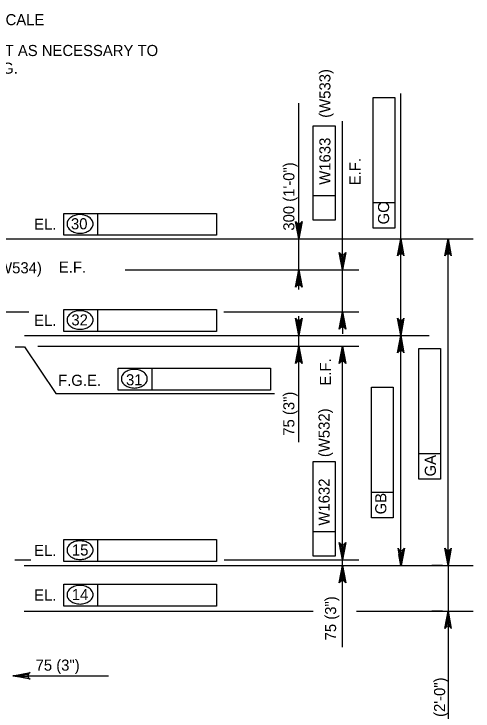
# Model space of a CAD drawing. Extents: x 634540 to 640306, y 296059 to 300275.
# Drawn here: x 638903.8 to 639027.8, y 296158.8 to 296347 of the extents above; entities that cross this region are included whole.
import ezdxf

# ---------------------------------------------------------------- set-up
doc = ezdxf.new("R2010")
doc.units = 0
doc.layers.add('3', color=7, linetype='Continuous')
doc.layers.add('4', color=7, linetype='Continuous')

msp = doc.modelspace()

# ---------------------------------------------------------------- linework, layer by layer
at = {"layer": '3'}
msp.add_line((638904.09, 296257.12), (638906.63, 296257.12), dxfattribs=at)
at = {"layer": '4'}
for p, q in [((639008.26, 296263.15), (639008.26, 296325.58)), ((639000.79, 296289.14), (639000.79, 296324.44)), ((639000.79, 296324.44), (639006.7, 296324.44)), ((639006.7, 296324.44), (639006.7, 296289.14)), ((638980.71, 296272.65), (638980.71, 296322.97)), ((638992.52, 296288.56), (638992.52, 296318.07)), ((638984.63, 296291.3), (638984.63, 296316.84)), ((638984.63, 296316.84), (638990.54, 296316.84)), ((638990.54, 296316.84), (638990.54, 296291.3)), ((638990.54, 296297.89), (638984.63, 296297.89)), ((639006.7, 296295.98), (639000.79, 296295.98)), ((638917.24, 296293.18), (638958.46, 296293.18)), ((638917.24, 296287.27), (638917.24, 296293.18)), ((638926.41, 296287.27), (638926.41, 296293.18)), ((638958.46, 296293.18), (638958.46, 296287.27)), ((638990.54, 296291.3), (638984.63, 296291.3)), ((638992.52, 296280.88), (638992.52, 296288.56)), ((639006.7, 296289.14), (639000.79, 296289.14)), ((638834.74, 296286.34), (639027.79, 296286.34)), ((638958.46, 296287.27), (638917.24, 296287.27)), ((639005.79, 296286.34), (639012.68, 296286.34)), ((639014.71, 296286.34), (639025.47, 296286.34)), ((639021.04, 296198.06), (639021.04, 296286.34)), ((638933.76, 296277.93), (638996.95, 296277.93)), ((638992.52, 296266.56), (638992.52, 296277.93)), ((638917.24, 296267.21), (638958.46, 296267.21)), ((638917.24, 296261.31), (638917.24, 296267.21)), ((638926.41, 296261.31), (638926.41, 296267.21)), ((638958.46, 296267.21), (638958.46, 296261.31)), ((638893.78, 296266.56), (638907.75, 296266.56)), ((638960.47, 296266.56), (638996.95, 296266.56)), ((638980.71, 296231.4), (638980.71, 296265.39)), ((638992.52, 296263.6), (638992.52, 296260.65)), ((638958.46, 296261.31), (638917.24, 296261.31)), ((638906.65, 296260.2), (639015.91, 296260.2)), ((639002.91, 296260.2), (639012.68, 296260.2)), ((638910.23, 296257.33), (638996.95, 296257.33)), ((638906.63, 296257.12), (638915.1, 296244.52)), ((639008.26, 296201.02), (639008.26, 296257.25)), ((639013.13, 296221.4), (639013.13, 296256.7)), ((639013.13, 296256.7), (639019.03, 296256.7)), ((639019.03, 296256.7), (639019.03, 296221.4)), ((638992.52, 296175.97), (638992.52, 296254.38)), ((638931.9, 296245.45), (638931.9, 296251.36)), ((638931.9, 296251.36), (638973.11, 296251.36)), ((638941.07, 296245.45), (638941.07, 296251.36)), ((638973.11, 296251.36), (638973.11, 296245.45)), ((639000.34, 296210.91), (639000.34, 296246.21)), ((639000.34, 296246.21), (639006.24, 296246.21)), ((639006.24, 296246.21), (639006.24, 296210.91)), ((638915.1, 296244.52), (638974.12, 296244.52)), ((638973.11, 296245.45), (638931.9, 296245.45)), ((639019.03, 296228.24), (639013.13, 296228.24)), ((638984.63, 296200.59), (638984.63, 296226.13)), ((638984.63, 296226.13), (638990.54, 296226.13)), ((638990.54, 296226.13), (638990.54, 296200.59)), ((639019.03, 296221.4), (639013.13, 296221.4)), ((639006.24, 296217.75), (639000.34, 296217.75)), ((639006.24, 296210.91), (639000.34, 296210.91)), ((638990.54, 296207.19), (638984.63, 296207.19)), ((638917.24, 296205.07), (638958.46, 296205.07)), ((638917.24, 296199.16), (638917.24, 296205.07)), ((638926.41, 296199.16), (638926.41, 296205.07)), ((638958.46, 296205.07), (638958.46, 296199.16)), ((638904.01, 296199.6), (638908.28, 296199.6)), ((638958.46, 296199.16), (638917.24, 296199.16)), ((638960.53, 296199.6), (638996.95, 296199.6)), ((638990.54, 296200.59), (638984.63, 296200.59)), ((638906.49, 296198.06), (639027.79, 296198.06)), ((639002.91, 296198.06), (639012.68, 296198.06)), ((639014.71, 296198.06), (639025.47, 296198.06)), ((639019.57, 296198.06), (639016.61, 296198.06)), ((639021.04, 296198.06), (639021.04, 296185.76)), ((638917.24, 296193.02), (638958.46, 296193.02)), ((638917.24, 296187.11), (638917.24, 296193.02)), ((638926.41, 296187.11), (638926.41, 296193.02)), ((638958.46, 296193.02), (638958.46, 296187.11)), ((638906.49, 296185.76), (638984.56, 296185.76)), ((638958.46, 296187.11), (638917.24, 296187.11)), ((638996.29, 296185.76), (639027.79, 296185.76)), ((639019.57, 296185.76), (639016.61, 296185.76)), ((639021.04, 296182.81), (639021.04, 296149.36)), ((638906.45, 296168.29), (638909.41, 296168.29)), ((638909.41, 296168.29), (638929.26, 296168.29))]:
    msp.add_line(p, q, dxfattribs=at)
for points in [[(638980.71, 296286.34), (638979.84, 296291), (638980.09, 296290.65), (638980.4, 296290.46), (638980.71, 296290.41), (638981.02, 296290.46), (638981.34, 296290.65), (638981.59, 296291), (638980.71, 296286.34), (638981.34, 296290.65), (638981.02, 296290.46), (638980.71, 296286.34), (638980.71, 296290.41), (638980.4, 296290.46), (638980.71, 296286.34), (638980.09, 296290.65)], [(639008.26, 296286.34), (639009.13, 296281.68), (639008.88, 296282.04), (639008.57, 296282.23), (639008.26, 296282.28), (639007.94, 296282.23), (639007.63, 296282.04), (639007.38, 296281.68), (639008.26, 296286.34), (639007.63, 296282.04), (639007.94, 296282.23), (639008.26, 296286.34), (639008.26, 296282.28), (639008.57, 296282.23), (639008.26, 296286.34), (639008.88, 296282.04)], [(639021.04, 296286.34), (639021.91, 296281.68), (639021.67, 296282.04), (639021.35, 296282.23), (639021.04, 296282.28), (639020.73, 296282.23), (639020.42, 296282.04), (639020.17, 296281.68), (639021.04, 296286.34), (639020.42, 296282.04), (639020.73, 296282.23), (639021.04, 296286.34), (639021.04, 296282.28), (639021.35, 296282.23), (639021.04, 296286.34), (639021.67, 296282.04)], [(638992.52, 296277.93), (638991.65, 296282.59), (638991.9, 296282.23), (638992.21, 296282.05), (638992.52, 296281.99), (638992.84, 296282.05), (638993.15, 296282.23), (638993.4, 296282.59), (638992.52, 296277.93), (638993.15, 296282.23), (638992.84, 296282.05), (638992.52, 296277.93), (638992.52, 296281.99), (638992.21, 296282.05), (638992.52, 296277.93), (638991.9, 296282.23)], [(638980.71, 296277.93), (638981.59, 296273.27), (638981.34, 296273.63), (638981.02, 296273.81), (638980.71, 296273.87), (638980.4, 296273.81), (638980.09, 296273.63), (638979.84, 296273.27), (638980.71, 296277.93), (638980.09, 296273.63), (638980.4, 296273.81), (638980.71, 296277.93), (638980.71, 296273.87), (638981.02, 296273.81), (638980.71, 296277.93), (638981.34, 296273.63)], [(638980.71, 296260.2), (638979.84, 296264.86), (638980.09, 296264.5), (638980.4, 296264.31), (638980.71, 296264.26), (638981.02, 296264.31), (638981.34, 296264.5), (638981.59, 296264.86), (638980.71, 296260.2), (638981.34, 296264.5), (638981.02, 296264.31), (638980.71, 296260.2), (638980.71, 296264.26), (638980.4, 296264.31), (638980.71, 296260.2), (638980.09, 296264.5)], [(638992.52, 296266.56), (638993.4, 296261.9), (638993.15, 296262.26), (638992.84, 296262.44), (638992.52, 296262.5), (638992.21, 296262.44), (638991.9, 296262.26), (638991.65, 296261.9), (638992.52, 296266.56), (638991.9, 296262.26), (638992.21, 296262.44), (638992.52, 296266.56), (638992.52, 296262.5), (638992.84, 296262.44), (638992.52, 296266.56), (638993.15, 296262.26)], [(639008.26, 296260.2), (639007.38, 296264.86), (639007.63, 296264.5), (639007.94, 296264.31), (639008.26, 296264.26), (639008.57, 296264.31), (639008.88, 296264.5), (639009.13, 296264.86), (639008.26, 296260.2), (639008.88, 296264.5), (639008.57, 296264.31), (639008.26, 296260.2), (639008.26, 296264.26), (639007.94, 296264.31), (639008.26, 296260.2), (639007.63, 296264.5)], [(639008.26, 296260.2), (639009.13, 296255.54), (639008.88, 296255.9), (639008.57, 296256.08), (639008.26, 296256.14), (639007.94, 296256.08), (639007.63, 296255.9), (639007.38, 296255.54), (639008.26, 296260.2), (639007.63, 296255.9), (639007.94, 296256.08), (639008.26, 296260.2), (639008.26, 296256.14), (639008.57, 296256.08), (639008.26, 296260.2), (639008.88, 296255.9)], [(638980.71, 296257.33), (638981.59, 296252.67), (638981.34, 296253.03), (638981.02, 296253.21), (638980.71, 296253.27), (638980.4, 296253.21), (638980.09, 296253.03), (638979.84, 296252.67), (638980.71, 296257.33), (638980.09, 296253.03), (638980.4, 296253.21), (638980.71, 296257.33), (638980.71, 296253.27), (638981.02, 296253.21), (638980.71, 296257.33), (638981.34, 296253.03)], [(638992.52, 296257.33), (638993.4, 296252.67), (638993.15, 296253.03), (638992.84, 296253.21), (638992.52, 296253.27), (638992.21, 296253.21), (638991.9, 296253.03), (638991.65, 296252.67), (638992.52, 296257.33), (638991.9, 296253.03), (638992.21, 296253.21), (638992.52, 296257.33), (638992.52, 296253.27), (638992.84, 296253.21), (638992.52, 296257.33), (638993.15, 296253.03)], [(638992.52, 296199.6), (638991.65, 296204.26), (638991.9, 296203.91), (638992.21, 296203.72), (638992.52, 296203.67), (638992.84, 296203.72), (638993.15, 296203.91), (638993.4, 296204.26), (638992.52, 296199.6), (638993.15, 296203.91), (638992.84, 296203.72), (638992.52, 296199.6), (638992.52, 296203.67), (638992.21, 296203.72), (638992.52, 296199.6), (638991.9, 296203.91)], [(639008.4, 296198.06), (639007.53, 296202.72), (639007.78, 296202.37), (639008.09, 296202.18), (639008.4, 296202.13), (639008.72, 296202.18), (639009.03, 296202.37), (639009.28, 296202.72), (639008.4, 296198.06), (639009.03, 296202.37), (639008.72, 296202.18), (639008.4, 296198.06), (639008.4, 296202.13), (639008.09, 296202.18), (639008.4, 296198.06), (639007.78, 296202.37)], [(639021.04, 296198.06), (639020.17, 296202.72), (639020.42, 296202.37), (639020.73, 296202.18), (639021.04, 296202.13), (639021.35, 296202.18), (639021.67, 296202.37), (639021.91, 296202.72), (639021.04, 296198.06), (639021.67, 296202.37), (639021.35, 296202.18), (639021.04, 296198.06), (639021.04, 296202.13), (639020.73, 296202.18), (639021.04, 296198.06), (639020.42, 296202.37)], [(638992.52, 296198.06), (638993.4, 296193.4), (638993.15, 296193.76), (638992.84, 296193.95), (638992.52, 296194), (638992.21, 296193.95), (638991.9, 296193.76), (638991.65, 296193.4), (638992.52, 296198.06), (638991.9, 296193.76), (638992.21, 296193.95), (638992.52, 296198.06), (638992.52, 296194), (638992.84, 296193.95), (638992.52, 296198.06), (638993.15, 296193.76)], [(639021.04, 296185.76), (639021.91, 296181.1), (639021.67, 296181.46), (639021.35, 296181.64), (639021.04, 296181.7), (639020.73, 296181.64), (639020.42, 296181.46), (639020.17, 296181.1), (639021.04, 296185.76), (639020.42, 296181.46), (639020.73, 296181.64), (639021.04, 296185.76), (639021.04, 296181.7), (639021.35, 296181.64), (639021.04, 296185.76), (639021.67, 296181.46)], [(638903.5, 296168.29), (638908.16, 296169.16), (638907.8, 296168.91), (638907.62, 296168.6), (638907.56, 296168.29), (638907.62, 296167.97), (638907.8, 296167.66), (638908.16, 296167.41), (638903.5, 296168.29), (638907.8, 296167.66), (638907.62, 296167.97), (638903.5, 296168.29), (638907.56, 296168.29), (638907.62, 296168.6), (638903.5, 296168.29), (638907.8, 296168.91)]]:
    msp.add_lwpolyline(points, dxfattribs=at)
for points in [[(639007.76, 296283.39), (639008.75, 296283.39), (639008.26, 296286.34)], [(639020.55, 296283.39), (639021.53, 296283.39), (639021.04, 296286.34)], [(638992.03, 296280.88), (638993.02, 296280.88), (638992.52, 296277.93)], [(638980.22, 296274.98), (638981.21, 296274.98), (638980.71, 296277.93)], [(638992.03, 296263.6), (638993.02, 296263.6), (638992.52, 296266.56)], [(638980.22, 296263.15), (638981.21, 296263.15), (638980.71, 296260.2)], [(639007.76, 296263.15), (639008.75, 296263.15), (639008.26, 296260.2)], [(639007.76, 296257.25), (639008.75, 296257.25), (639008.26, 296260.2)], [(638980.22, 296254.38), (638981.21, 296254.38), (638980.71, 296257.33)], [(638992.03, 296254.38), (638993.02, 296254.38), (638992.52, 296257.33)], [(638992.03, 296202.56), (638993.02, 296202.56), (638992.52, 296199.6)], [(639007.76, 296201.02), (639008.75, 296201.02), (639008.26, 296198.06)], [(639020.55, 296201.02), (639021.53, 296201.02), (639021.04, 296198.06)], [(638992.03, 296195.11), (638993.02, 296195.11), (638992.52, 296198.06)], [(639020.55, 296182.81), (639021.53, 296182.81), (639021.04, 296185.76)], [(638906.45, 296168.78), (638906.45, 296167.79), (638903.5, 296168.29)]]:
    msp.add_lwpolyline(points, close=True, dxfattribs=at)
for centre, radius, start, end in [((638919.94, 296290.33), 1.83, 149.9767, 180), ((638920.75, 296289.87), 2.76, 125.6316, 149.9767), ((638921.28, 296289.13), 3.66, 106.5358, 125.6316), ((638921.62, 296287.97), 4.87, 90, 106.5358), ((638921.62, 296287.97), 4.87, 73.4642, 90), ((638921.97, 296289.13), 3.66, 54.3684, 73.4642), ((638922.49, 296289.87), 2.76, 30.0233, 54.3684), ((638923.3, 296290.33), 1.83, 0, 30.0233), ((638919.94, 296290.33), 1.83, 180, 210.0233), ((638920.75, 296290.8), 2.76, 210.0233, 234.3684), ((638922.49, 296290.8), 2.76, 305.6316, 329.9767), ((638923.3, 296290.33), 1.83, 329.9767, 0), ((638921.28, 296291.53), 3.66, 234.3684, 253.4642), ((638921.62, 296292.69), 4.87, 253.4642, 270), ((638921.62, 296292.69), 4.87, 270, 286.5358), ((638921.97, 296291.53), 3.66, 286.5358, 305.6316), ((638921.28, 296263.17), 3.66, 106.5358, 125.6316), ((638921.62, 296262.01), 4.87, 90, 106.5358), ((638921.62, 296262.01), 4.87, 73.4642, 90), ((638921.97, 296263.17), 3.66, 54.3684, 73.4642), ((638919.94, 296264.37), 1.83, 149.9767, 180), ((638920.75, 296263.9), 2.76, 125.6316, 149.9767), ((638922.49, 296263.9), 2.76, 30.0233, 54.3684), ((638923.3, 296264.37), 1.83, 0, 30.0233), ((638919.94, 296264.37), 1.83, 180, 210.0233), ((638920.75, 296264.83), 2.76, 210.0233, 234.3684), ((638922.49, 296264.83), 2.76, 305.6316, 329.9767), ((638923.3, 296264.37), 1.83, 329.9767, 0), ((638921.28, 296265.57), 3.66, 234.3684, 253.4642), ((638921.62, 296266.73), 4.87, 253.4642, 270), ((638921.62, 296266.73), 4.87, 270, 286.5358), ((638921.97, 296265.57), 3.66, 286.5358, 305.6316), ((638935.41, 296248.05), 2.76, 125.6316, 149.9767), ((638935.93, 296247.31), 3.66, 106.5358, 125.6316), ((638936.28, 296246.15), 4.87, 90, 106.5358), ((638936.28, 296246.15), 4.87, 73.4642, 90), ((638936.62, 296247.31), 3.66, 54.3684, 73.4642), ((638937.15, 296248.05), 2.76, 30.0233, 54.3684), ((638934.6, 296248.51), 1.83, 149.9767, 180), ((638934.6, 296248.51), 1.83, 180, 210.0233), ((638937.96, 296248.51), 1.83, 0, 30.0233), ((638937.96, 296248.51), 1.83, 329.9767, 0), ((638935.41, 296248.98), 2.76, 210.0233, 234.3684), ((638935.93, 296249.71), 3.66, 234.3684, 253.4642), ((638936.28, 296250.87), 4.87, 253.4642, 270), ((638936.28, 296250.87), 4.87, 270, 286.5358), ((638936.62, 296249.71), 3.66, 286.5358, 305.6316), ((638937.15, 296248.98), 2.76, 305.6316, 329.9767), ((638921.62, 296199.86), 4.87, 90, 106.5358), ((638921.62, 296199.86), 4.87, 73.4642, 90), ((638919.94, 296202.22), 1.83, 149.9767, 180), ((638920.75, 296201.76), 2.76, 125.6316, 149.9767), ((638921.28, 296201.02), 3.66, 106.5358, 125.6316), ((638921.97, 296201.02), 3.66, 54.3684, 73.4642), ((638922.49, 296201.76), 2.76, 30.0233, 54.3684), ((638923.3, 296202.22), 1.83, 0, 30.0233), ((638919.94, 296202.22), 1.83, 180, 210.0233), ((638920.75, 296202.69), 2.76, 210.0233, 234.3684), ((638922.49, 296202.69), 2.76, 305.6316, 329.9767), ((638923.3, 296202.22), 1.83, 329.9767, 0), ((638921.28, 296203.42), 3.66, 234.3684, 253.4642), ((638921.62, 296204.58), 4.87, 253.4642, 270), ((638921.62, 296204.58), 4.87, 270, 286.5358), ((638921.97, 296203.42), 3.66, 286.5358, 305.6316), ((638920.75, 296189.7), 2.76, 125.6316, 149.9767), ((638921.28, 296188.97), 3.66, 106.5358, 125.6316), ((638921.62, 296187.81), 4.87, 90, 106.5358), ((638921.62, 296187.81), 4.87, 73.4642, 90), ((638921.97, 296188.97), 3.66, 54.3684, 73.4642), ((638922.49, 296189.7), 2.76, 30.0233, 54.3684), ((638919.94, 296190.17), 1.83, 149.9767, 180), ((638919.94, 296190.17), 1.83, 180, 210.0233), ((638923.3, 296190.17), 1.83, 0, 30.0233), ((638923.3, 296190.17), 1.83, 329.9767, 0), ((638920.75, 296190.64), 2.76, 210.0233, 234.3684), ((638921.28, 296191.37), 3.66, 234.3684, 253.4642), ((638921.62, 296192.53), 4.87, 253.4642, 270), ((638921.62, 296192.53), 4.87, 270, 286.5358), ((638921.97, 296191.37), 3.66, 286.5358, 305.6316), ((638922.49, 296190.64), 2.76, 305.6316, 329.9767)]:
    msp.add_arc(centre, radius, start, end, dxfattribs=at)

# ---------------------------------------------------------------- texts
for s, height, p in [('NO SCALE', 3, (638891.69, 296344)), ('ADJUST REINFORCEMENT AS NECESSARY TO', 3.0001, (638851.99, 296335.67)), ('ACCOMMODATE OPENING.', 3.0001, (638851.99, 296330.89)), ('EL.', 3, (638909.22, 296288.76)), ('30', 3, (638919.16, 296288.87)), ('(W534)', 3, (638898.15, 296276.99)), ('E.F.', 3, (638915.9, 296277.15)), ('EL.', 3, (638909.22, 296262.79)), ('32', 3, (638919.27, 296262.91)), ('31', 3, (638934.04, 296246.73)), ('F.G.E.', 3, (638915.68, 296246.59)), ('EL.', 3, (638909.22, 296200.65)), ('15', 3, (638919.41, 296200.76)), ('EL.', 3, (638909.22, 296188.59)), ('14', 3, (638919.38, 296188.71)), ('75 (3")', 3, (638909.61, 296169.66))]:
    msp.add_text(s, height=height, dxfattribs=at).set_placement(p)
for s, height, p in [('(W533)', 3, (638989.27, 296318.99)), ('W1633', 3, (638989.27, 296300.91)), ('300 (1\'-0")', 3.0001, (638979.52, 296288.5)), ('E.F.', 3, (638997.4, 296300.79)), ('GC', 3, (639005.11, 296290.2)), ('E.F.', 3, (638989.4, 296246.67)), ('75 (3")', 3, (638979.52, 296233.12)), ('(W532)', 3, (638989.05, 296227.35)), ('GA', 3, (639017.75, 296222.12)), ('W1632', 3, (638989.05, 296208.85)), ('GB', 3, (639004.36, 296211.89)), ('75 (3")', 3, (638990.8, 296177.85)), ('600 (2\'-0")', 3.0001, (639020.24, 296149.36))]:
    msp.add_text(s, height=height, rotation=90, dxfattribs=at).set_placement(p)

doc.saveas('drawing.dxf')
